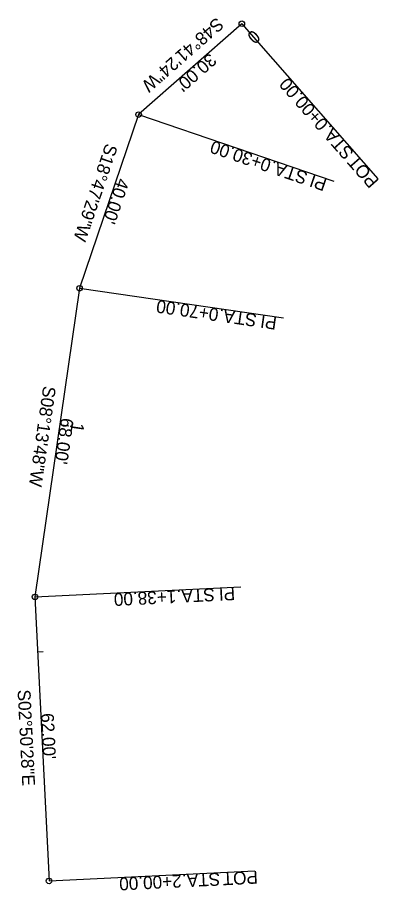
# Model space of a CAD drawing. Extents: x 223919 to 223998, y 387160 to 387350.
import ezdxf

# ---------------------------------------------------------------- set-up
doc = ezdxf.new("R2010")
doc.units = 0
for name, color, linetype in [('DR_X_Elev_Flow', 7, 'Continuous'), ('RD_X_Cells', 7, 'Continuous'), ('SV_X_Random_Point', 7, 'Continuous'), ('SV_X_Shot_Marker', 7, 'Continuous'), ('UT_X_Electric_Cells', 7, 'Continuous')]:
    doc.layers.add(name, color=color, linetype=linetype)

msp = doc.modelspace()

# ---------------------------------------------------------------- linework, layer by layer
at = {"layer": 'RD_X_Cells'}
for p, q in [((223967.91, 387349.12), (223969.23, 387347.62)), ((223938.94, 387310.38), (223940.07, 387309.99)), ((223928.2, 387261.75), (223930.18, 387261.47)), ((223923.36, 387212.16), (223924.55, 387212.22))]:
    msp.add_line(p, q, dxfattribs=at)
at = {"layer": 'SV_X_Random_Point'}
for p, q in [((223967.91, 387349.12), (223997.62, 387315.32)), ((223945.38, 387329.31), (223987.98, 387314.82)), ((223932.5, 387291.45), (223977.03, 387285)), ((223922.76, 387224.15), (223967.71, 387226.38)), ((223925.83, 387162.22), (223970.78, 387164.45))]:
    msp.add_line(p, q, dxfattribs=at)
for centre in [(223967.91, 387349.12), (223945.38, 387329.31), (223932.5, 387291.45), (223922.76, 387224.15), (223925.83, 387162.22)]:
    msp.add_circle(centre, 0.6, dxfattribs=at)
at = {"layer": 'UT_X_Electric_Cells'}
for p, q in [((223967.91, 387349.12), (223945.38, 387329.31)), ((223945.38, 387329.31), (223932.5, 387291.45)), ((223932.5, 387291.45), (223922.76, 387224.15)), ((223922.76, 387224.15), (223925.83, 387162.22))]:
    msp.add_line(p, q, dxfattribs=at)

# ---------------------------------------------------------------- texts
at = {"layer": 'DR_X_Elev_Flow'}
for s, rotation, p in [("30.00'", 221.3099, (223960.85, 387342.86)), ("40.00'", 251.2085, (223940.77, 387315.63)), ("68.00'", 261.77, (223928.47, 387263.29)), ("62.00'", 272.8411, (223924.06, 387198.74))]:
    msp.add_text(s, height=2.8, rotation=rotation, dxfattribs=at).set_placement(p)
at = {"layer": 'RD_X_Cells'}
for s, rotation, p in [('0', 221.3099, (223970.4, 387347.97)), ('1', 261.77, (223930.81, 387262.3))]:
    msp.add_text(s, height=2.8, rotation=rotation, dxfattribs=at).set_placement(p)
at = {"layer": 'SV_X_Random_Point'}
for s, rotation, p in [('0+00.00', 131.3099, (223986.97, 387327.37)), (' STA. ', 131.3099, (223993.21, 387320.27)), ('0+30.00', 161.2085, (223974.54, 387319.35)), (' STA. ', 161.2085, (223983.49, 387316.3)), ('POT', 131.3099, (223997.96, 387314.86)), ('PI', 161.2085, (223986.7, 387315.21)), ('0+70.00', 171.77, (223962.99, 387286.99)), (' STA. ', 171.77, (223972.34, 387285.64)), ('PI', 171.77, (223975.7, 387285.15)), ('1+38.00', 182.8411, (223953.54, 387225.63)), (' STA. ', 182.8411, (223962.98, 387226.1)), ('PI', 182.8411, (223966.37, 387226.27)), (' STA. ', 182.8411, (223964.15, 387164.08)), ('POT', 182.8411, (223971.34, 387164.44)), ('2+00.00', 182.8411, (223954.71, 387163.61))]:
    msp.add_text(s, height=2.8, rotation=rotation, dxfattribs=at).set_placement(p)
at = {"layer": 'SV_X_Shot_Marker'}
for s, rotation, p in [('S48°41\'24"W', 221.3099, (223962.41, 387350.67)), ('S18°47\'29"W', 251.2085, (223938.22, 387323.18)), ('S08°13\'48"W', 261.77, (223924.58, 387270.25)), ('S02°50\'28"E', 272.8411, (223918.96, 387203.87))]:
    msp.add_text(s, height=2.8, rotation=rotation, dxfattribs=at).set_placement(p)

doc.saveas('drawing.dxf')
